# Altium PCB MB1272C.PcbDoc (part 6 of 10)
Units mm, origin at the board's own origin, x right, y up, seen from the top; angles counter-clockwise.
Board outline 101 x 71 mm, 6 copper layers (Top Layer, Signal Layer 1, Signal Layer 2, Signal Layer 3, Signal Layer 4, Bottom Layer), stack 1.552 mm thick; 520 components, 478 nets, 2156 pads, 1894 vias.
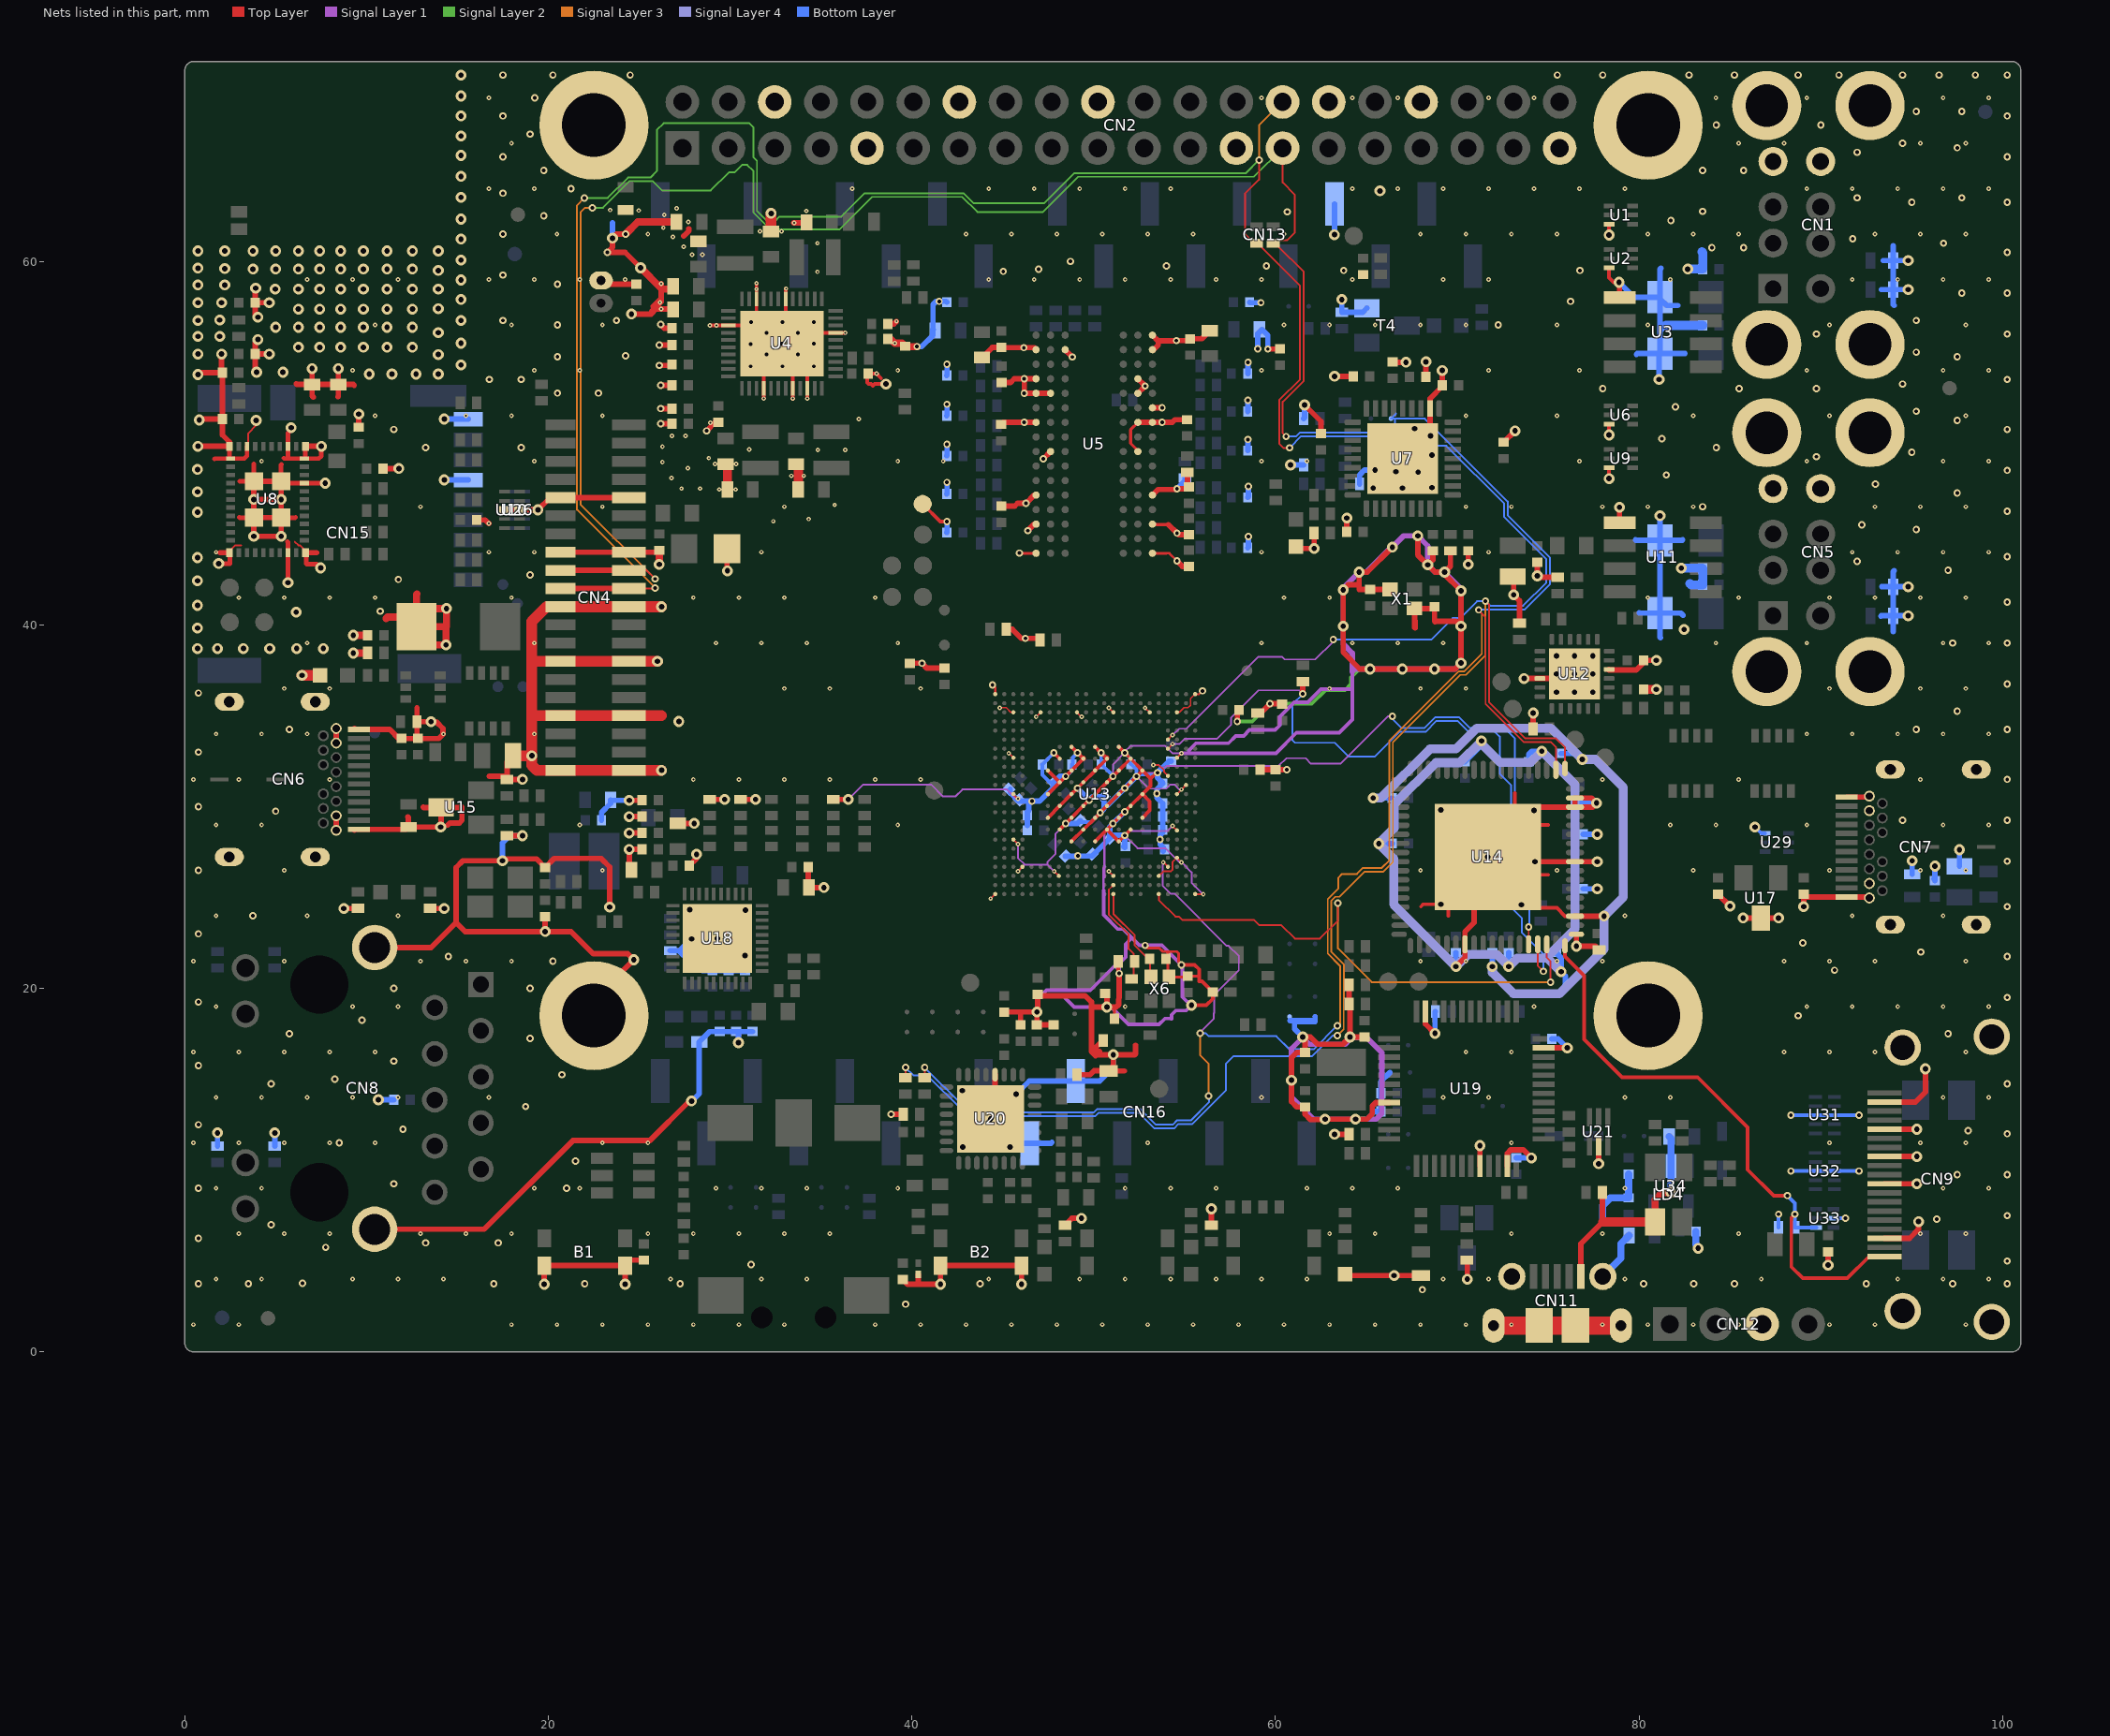
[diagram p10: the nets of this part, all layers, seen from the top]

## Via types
v1: diameter 0.4, hole 0.2, Top Layer to Bottom Layer, tented both sides, 912 vias
v2: diameter 0.25, hole 0.1, Top Layer to Signal Layer 1, tented top, 493 vias
v3: diameter 0.6, hole 0.3, Top Layer to Bottom Layer, tented both sides, 452 vias
v4: diameter 0.25, hole 0.1, Top Layer to Signal Layer 1, tented both sides, 37 vias

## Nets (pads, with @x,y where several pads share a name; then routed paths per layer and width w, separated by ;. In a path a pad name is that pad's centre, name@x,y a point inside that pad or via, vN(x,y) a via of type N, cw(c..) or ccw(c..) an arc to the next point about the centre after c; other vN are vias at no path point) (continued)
GND: B1.1 B1.2 B2.3 B2.4 C1.1 C2.1 C3.1 C4.1 C5.1 C6.1 C7.1 C8.1 C9.1 C10.2 C11.1 C12.1 C13.1 C14.2 C15.1 C16.1 C17.2 C18.1 C19.1 C20.1 C21.1 C22.2 C23.1 C24.1 C25.1 C26.1 C27.1 C28.1 C29.1 C30.1 C31.1 C32.1 C33.1 C34.1 C35.2 C36.2 C37.1 C38.1 C39.1 C40.1 C41.1 C42.1 C43.1 C44.1 C45.1 C46.2 C47.2 C48.2 C49.1 C50.1 C51.1 C52.2 C53.1 C54.1 C55.1 C56.1 C57.2 C58.1 C59.1 C60.2 C61.2 C62.1 C63.1 C64.1 C65.1 C67.1 C68.1 C69.1 C70.2 C71.1 C72.1 C73.1 C74.1 C75.1 C76.2 C77.1 C78.1 C79.1 C80.1 C81.1 C82.1 C83.1 C84.1 C85.1 C86.1 C87.2 C88.1 C89.1 C90.2 C91.2 C92.1 C93.1 C94.1 C95.1 C96.2 C98.2 C99.2 C112.1 C114.1 C115.1 C117.1 C118.1 C119.2 C120.2 C121.1 C122.1 C123.1 C124.1 C125.2 C126.2 C127.2 C128.2 C129.2 C130.2 C131.2 C132.2 C133.1 C134.2 C135.2 C136.1 C137.1 C138.1 C139.1 C140.1 C141.1 C142.1 C143.1 C144.1 C145.1 C146.1 C147.1 C148.1 C149.1 C150.1 C151.1 C152.1 C153.1 C154.1 C155.1 C156.1 C157.1 C158.1 C159.1 C160.1 C161.1 C162.1 C163.1 C164.1 C165.1 C166.1 C167.1 C168.1 C169.1 C170.1 C171.1 C172.1 C173.1 C174.1 C175.1 C176.1 C177.1 C178.1 C179.1 C180.1 C181.1 C182.1 C183.1 C184.1 C185.2 C186.1 C187.1 C188.1 C189.1 C190.1 C191.1 C192.1 C300.1 CN1.B4 CN1.CH1 CN1.CH2 CN1.CH3 CN1.CH4 CN1.T4 CN2.6 CN2.9 CN2.14 CN2.20 CN2.25 CN2.30 CN2.34 CN2.39 CN3.2 CN4.1 CN4.4 CN4.7 CN4.10 CN4.13 CN4.16 CN5.B4 CN5.CH1 CN5.CH2 CN5.CH3 CN5.CH4 CN5.T4 CN6.A1 CN6.A12 CN6.B1 CN6.B12 CN6.SH1 CN6.SH2 CN6.SH3 CN6.SH4 CN7.A1 CN7.A12 CN7.B1 CN7.B12 CN7.SH1 CN7.SH2 CN7.SH3 CN7.SH4 CN8.15 CN8.16 CN9.2 CN9.5 CN9.8 CN9.11 CN9.17 CN9.20 CN9.21 CN9.22 CN9.23 CN11.5 CN11.6 CN11.7 CN11.8 CN11.9 CN11.10 CN11.11 CN12.3 CN13.7 CN15.6 CN15.9 CN16.6 CN16.7 H1.1 H2.1 H3.1 H4.1 LD1.2 LD2.2 LD4.1 LD7.2 LD8.2 R15.1 R23.1 R24.1 R31.1 R36.1 R37.1 R38.2 R39.1 R44.1 R45.1 R46.1 R48.1 R50.1 R51.1 R54.1 R57.1 R66.1 R67.1 R70.2 R80.1 R81.2 R82.1 R83.2 R84.1 R87.2 R91.1 R100.1 R110.2 R111.2 R112.1 R119.1 R129.1 R136.1 R137.1 R139.1 R149.1 R155.2 R159.1 R162.1 R163.1 R164.1 R303.2 SB11.1 SB12.1 SB18.1 T4.2 TP2.1 U1.3 U2.3 U3.1 U4.6 U4.10 U4.15 U4.26 U4.30 U4.32 U4.41 U4.ep U5.A9 U5.B1 U5.B3 U5.B9 U5.D1 U5.D8 U5.E1 U5.E2 U5.E8 U5.F9 U5.G1 U5.G8 U5.G9 U5.J2 U5.J8 U5.M1 U5.M9 U5.P1 U5.P9 U5.T1 U5.T9 U6.3 U7.11 U7.37 U8.1 U8.12 U8.19 U8.21 U8.29 U8.32 U8.33 U8.35 U8.40 U8.42 U8.43 U8.44 U8.45 U8.46 U9.3 U10.3 U10.8 U11.1 U12.10 U12.22 U12.ep U13.1A3 U13.1A5 U13.1A7 U13.1B2 U13.1B4 U13.1B6 U13.1B8 U13.1C1 U13.1C3 U13.1C5 U13.1C7 U13.1C9 U13.1D2 U13.1D4 U13.1D6 U13.1D8 U13.1E1 U13.1E3 U13.1E5 U13.1E7 U13.1E9 U13.1F2 U13.1F4 U13.1F6 U13.1F8 U13.1G1 U13.1G3 U13.1G5 U13.1G7 U13.1G9 U13.1H2 U13.1H4 U13.1H6 U13.1H8 U13.1J3 U13.1J5 U13.1J7 U13.A1 U13.A23 U13.AA5 U13.AA8 U13.AA12 U13.AA16 U13.AA21 U13.AB13 U13.AC1 U13.AC23 U13.C7 U13.C12 U13.C16 U13.C21 U13.D4 U13.F21 U13.H3 U13.K21 U13.P3 U13.P21 U13.V21 U13.W3 U14.43 U14.55 U14.57 U14.63 U14.69 U14.70 U14.e-Pad U15.3 U16.2 U17.3 U18.41 U19.8 U19.20 U19.23 U19.35 U19.47 U20.28 U20.33 U21.2 U23.2 U24.2 U25.2 U26.3 U26.8 U27.2 U28.2 U29.3 U30.2 U31.3 U31.8 U32.3 U32.8 U33.2 U34.2 U35.2 X1.2 X1.4 X6.2 | length 990.5
  Top Layer w0.09: v4(44.83,35.44) 45.191,35.44 45.441,35.19 U13.C21@45.58,35.19 ; U13.W3@53.58,26.19 53.83,26.44 54.178,26.44 ; 54.184,26.44 54.245,26.44 54.33,26.525 54.33,26.955 54.565,27.19 U13.AA5@54.58,27.19 ; U13.AA21@54.59,35.186 54.708,35.186 54.962,35.44 55.185,35.44 55.325,35.575 ; 55.33,35.575 55.33,35.949 55.571,36.19 U13.AC23@55.58,36.19
  Top Layer w0.1: U8.12@2.463,43.975 2.463,44.063 2.775,44.375 3.1,44.375 ; U8.40@3.425,49.825 3.425,50 3.49,50.065 3.49,50.535 3.925,50.97 v3(3.925,51.25) ; 6.05,44.575 6.25,44.375 6.325,44.375 6.638,44.063 U8.21@6.638,43.975 ; v2(44.33,24.94) U13.A1@44.58,25.19 ; v2(45.33,32.94) U13.C16@45.58,32.69 ; U13.C7@45.58,28.19 v2(45.83,27.94) ; U13.C12@45.58,30.69 v2(45.83,30.44) ; v2(45.83,26.44) U13.D4@46.08,26.69 ; v2(46.83,34.94) U13.F21@47.08,35.19 ; v2(47.83,26.44) U13.H3@48.08,26.19 ; U13.K21@49.08,35.19 v4(49.33,34.94) ; v2(50.83,26.44) U13.P3@51.08,26.19 ; v4(50.83,35.44) U13.P21@51.08,35.19 ; v4@52.84,35.43 U13.V21@53.08,35.19 ; v2(54.33,28.94) U13.AA8@54.58,28.69 ; U13.AA5@54.58,27.19 v2(54.83,26.94) ; U13.AA12@54.58,30.69 v2(54.83,30.94) U13.AB13@55.08,31.19 ; U13.AA16@54.58,32.69 v2(54.83,32.94) ; U13.AC1@55.58,25.19 55.595,25.175 v4(56.025,25.175) ; U13.AC23@55.58,36.19 55.8,36.19 v1(55.98,36.37)
  Top Layer w0.12: v1(44.43,36.7) 44.58,36.55 U13.A23@44.58,36.19 ; v1@48.772,54.74 v1@48.772,54.798 ; U5.J8@52.43,49.54 U5.J8@52.43,49.59 ; 54.01,43.94 54.16,43.94 v1(54.58,43.52)
  Top Layer w0.15: v1@45.91,43.94 U5.T1@46.83,43.94 ; C300.1@51.15,18.325 51.15,18.9 51.225,18.975 ; v1@52.83,22.34 52.945,22.225 53.605,22.225 53.805,22.025 54.572,22.025 54.68,21.917 54.68,21.44 v1(54.83,21.29) ; U5.T9@53.18,43.94 U5.T9@53.23,43.94 54.01,43.94 ; 54.075,21.98 54.075,20.7 X6.2@54.15,20.625 54.925,20.625 54.975,20.675 C87.2@55.175,20.675 55.75,20.675 55.8,20.625
  Top Layer w0.16: U5.J8@52.43,49.59 52.03,49.99 52.03,50.74 U5.G8@52.43,51.14
  Top Layer w0.2: v4(28.882,56.482) 29.243,56.482 v4(29.25,56.475) U4.15@29.9,56.475 30.875,56.475 U4.ep@30.9,56.45 ; v2(31.45,58.8) v2(31.45,58.475) U4.10@31.45,57.925 31.45,56.875 v1(32.85,55.475) ; v2(31.85,52.45) U4.26@31.85,53.025 31.85,54.475 v1(32.85,55.475) ; v3(32.255,62.64) v3@32.381,62.514 ; v2@33.05,58.5 U4.6@33.05,57.925 U4.ep@33.05,55.675 ; v2@33.45,52.425 v2(33.45,52.45) U4.30@33.45,53.025 U4.ep@33.45,54.875 ; v2(34.25,52.45) U4.32@34.25,53.025 34.25,54.075 U4.ep@33.45,54.875 ; v2(36.325,56.075) U4.41@35.8,56.075 33.45,56.075 U4.ep@33.05,55.675 ; C26.1@37.537,53.762 37.537,53.338 37.625,53.25 37.757,53.25 37.857,53.15 37.957,53.25 v3(38.575,53.25) ; C26.1@37.6,53.825 v2(38.05,53.825) 38.3,53.575 ; C63.1@39.85,37.91 C63.1@39.87,37.89 ; TP2.1@40.592,46.652 41.554,45.69 v1(41.93,45.69) ; U13.1A5@47.475,30.675 47.475,30.685 U13.1B6@48.12,31.33 ; U13.1A7@47.48,31.99 U13.1B6@48.13,31.34 ; U13.1A3@47.5,29.41 U13.1B4@48.13,30.04 ; v1@47.8,32.95 47.82,32.95 U13.1B8@48.13,32.64 ; U13.1B4@48.12,30.05 48.14,30.05 U13.1C5@48.78,30.69 v1(49.105,31.015) U13.1D6@49.43,31.34 50.05,31.96 U13.1E7@50.05,32.01 ; U13.1B6@48.12,31.35 U13.1B6@48.12,31.33 ; U13.1B2@48.13,28.74 U13.1C3@48.78,29.39 U13.1D4@49.43,30.04 U13.1E5@50.08,30.69 U13.1F6@50.73,31.34 v1(51.055,31.665) U13.1G7@51.38,31.99 U13.1H8@52.03,32.64 ; U13.1C1@48.78,28.09 U13.1D2@49.43,28.74 U13.1E3@50.08,29.39 U13.1F4@50.73,30.04 U13.1G5@51.38,30.69 v1(51.705,31.015) U13.1H6@52.03,31.34 U13.1J7@52.68,31.99 ; U13.1C7@48.78,32 U13.1C7@48.78,31.99 ; U13.1C9@48.78,33.29 v1@49.11,32.96 ; v1@49.1,32.98 U13.1D8@49.42,32.66 ; U13.1D8@49.43,32.65 U13.1D8@49.42,32.66 ; U13.1E9@50.07,33.29 v1@50.395,32.965 ; U13.1E1@50.08,28.09 U13.1F2@50.73,28.74 ; U13.1E7@50.08,32 50.09,32 U13.1F8@50.73,32.64 ; v1(50.405,32.965) U13.1F8@50.7,32.67 ; R303.2@51.35,21.35 51.35,20.55 51.4,20.5 ; U13.1G9@51.38,33.29 v1(51.705,32.965) U13.1H8@52.03,32.64 ; U13.1H2@52.03,28.74 v1(51.705,28.415) U13.1G1@51.38,28.09 U13.1F2@50.73,28.74 ; U13.1J3@52.68,29.39 53.075,29.785 53.075,30.295 U13.1J5@52.68,30.69 ; U5.P9@53.23,45.54 53.25,45.52 54.11,45.52 ; v1(53.505,31.865) 53.445,31.865 53.125,31.545 ; 54.075,21.98 54.095,22 ; v1(54.83,21.29) 55.555,21.29 55.8,21.045 55.8,20.625 55.8,20.4 55.95,20.4 C89.1@56.55,19.8 56.55,19.425 56.2,19.075 v3(55.375,19.075) ; v1(59.7,35.66) 59.73,35.63 C67.1@60.33,35.63 ; C67.1@60.3,35.66 C67.1@60.33,35.63 ; C67.1@60.34,35.62 C67.1@60.33,35.63 ; C67.1@60.36,35.63 C67.1@60.33,35.63 ; 68,24.5 68.125,24.625 v3(69.1,24.625) ; 69.5,24 69.5,25.05 70.925,26.475 v3(71.675,27.225) ; 73.156,30.75 U14.e-Pad@73.156,28.706 ; 75,26.25 U14.e-Pad@72.65,26.25 ; 75,29 73.45,29 U14.e-Pad@73.156,28.706 ; U14.57@76.475,23.975 75.925,23.975 75.475,24.425 74.475,24.425 U14.e-Pad@72.65,26.25 ; v3(78.35,48.05) U9.3@78.35,48.65 ; v3(78.35,50.45) U6.3@78.35,51.05 ; U2.3@78.35,59.65 78.35,59.1 78.6,58.85 v3(78.9,58.85) ; v3(78.35,61.45) U1.3@78.35,62.05 ; v1(32.85,55.475) U4.ep@33.05,55.675 ; v1(32.85,55.475) U4.ep@33.45,54.875 ; U13.1B6@48.12,31.33 U13.1B6@48.13,31.34 ; U13.1B6@48.13,31.34 U13.1C7@48.78,31.99 ; U13.1C7@48.78,31.99 49.42,32.63 U13.1D8@49.42,32.66 ; U13.1F2@50.73,28.74 v1(51.055,29.065) U13.1G3@51.38,29.39 v1(51.705,29.715) U13.1H4@52.03,30.04 U13.1J5@52.68,30.69 ; U13.1H8@52.03,32.64 U13.1J7@52.68,31.99 ; U13.1J5@52.68,30.69 53.125,31.135 53.125,31.545 ; U13.1J7@52.68,31.99 53.125,31.545 ; v3(71.675,27.225) U14.e-Pad@73.156,28.706 ; v3(71.675,27.225) U14.e-Pad@72.65,26.25
  Top Layer w0.25: 1.625,49.125 1.65,49.15 U8.1@2.525,49.15 ; v3(1.863,43.375) 2.475,43.375 2.475,43.963 U8.12@2.463,43.975 ; U8.42@2.463,49.825 2.463,49.212 U8.1@2.525,49.15 ; 3,45.925 3.025,45.9 3.775,45.9 U8.44@3.8,45.9 ; 3.025,47.9 U8.43@3.8,47.9 3.8,48.85 ; U8.40@3.425,49.825 3.425,49.3 3.275,49.15 U8.1@2.525,49.15 ; U8.46@5.3,45.9 6.075,45.9 6.1,45.925 ; 5.325,48.825 5.3,48.8 U8.45@5.3,47.9 5.4,47.8 U8.29@6.575,47.8 v3(7.725,47.8) ; 5.45,49.175 5.475,49.15 U8.32@6.575,49.15 ; 5.65,44.575 5.675,44.55 U8.19@5.675,43.975 v3(5.675,42.325) ; 5.675,49.25 U8.35@5.675,49.825 5.675,50.55 5.85,50.725 v3(5.85,50.85) ; U8.21@6.638,43.975 6.675,43.937 6.675,43.375 6.703,43.347 7.266,43.347 v3(7.475,43.137) ; U8.33@6.638,49.825 6.638,49.212 U8.32@6.575,49.15 ; v3(7.512,49.825) 7.512,49.287 7.375,49.15 U8.32@6.575,49.15
  Top Layer w0.3: v3(0.725,49.825) U8.42@2.463,49.825 2.463,50.062 2.075,50.45 C34.1@2.075,51.325 ; v3(0.725,53.775) 0.825,53.875 C24.1@2.075,53.875 ; v3(0.8,51.275) 0.875,51.275 0.925,51.325 C34.1@2.075,51.325 ; 1.95,43.975 U8.12@2.463,43.975 ; v3(2.025,54.9) 2.025,53.925 C24.1@2.075,53.875 ; v3@3.875,55.55 C19.1@3.875,54.9 ; v3@3.875,57.075 C8.1@3.875,57.725 ; v3@3.875,58.375 C8.1@3.875,57.725 ; v3(3.95,53.9) 3.875,53.975 C19.1@3.875,54.9 ; v3(4.65,54.9) C19.1@3.875,54.9 ; v3(4.65,57.725) C8.1@3.875,57.725 ; v3(5.3,46.9) U8.45@5.3,47.9 U8.43@3.8,47.9 v3(3.8,46.9) ; 6.125,53.275 6.175,53.225 C28.1@7,53.225 ; U8.21@6.638,43.975 7.25,43.975 ; U8.33@6.638,49.825 v3(7.512,49.825) ; v3(7,54.1) C28.1@7,53.225 ; 7.075,52.525 7,52.6 C28.1@7,53.225 ; CN6.B1@8.33,28.7 CN6.B1@8.33,29.5 ; CN6.B12@8.33,33.5 CN6.B12@8.33,34.3 ; 8.425,52.55 8.45,52.575 C29.1@8.45,53.225 ; v3(8.45,54.1) C29.1@8.45,53.225 ; v3(8.75,24.4) R66.1@9.525,24.4 ; 9.325,53.175 9.275,53.225 C29.1@8.45,53.225 ; CN6.A12@9.33,28.7 9.38,28.75 CN6.A12@9.58,28.75 12.175,28.75 U16.2@12.3,28.875 ; CN6.A1@9.33,34.3 9.38,34.25 CN6.A1@9.58,34.25 11.275,34.25 11.775,33.75 C69.1@11.925,33.75 C70.2@12.825,33.75 ; C37.1@9.575,50.875 v3(9.575,51.6) ; CN8.15@10.45,6.75 16.475,6.75 21.35,11.625 25.576,11.625 27.751,13.8 v3(27.875,13.8) ; CN8.16@10.45,22.25 13.55,22.25 14.925,23.625 ; C45.1@10.9,48.6 v3(11.775,48.6) ; 12.275,29.425 12.3,29.4 U16.2@12.3,28.875 ; 12.775,35.425 R45.1@12.775,34.675 ; 13.125,29.975 13.15,29.95 U15.3@14.1,29.95 ; R67.1@13.5,24.4 v3(14.275,24.4) ; 14.467,28.983 14.584,29.1 15.1,29.1 15.25,29.25 15.25,29.975 15.225,29.95 U15.3@14.1,29.95 ; C49.1@16.05,45.775 16.525,45.775 v4(16.725,45.575) ; 16.75,31.675 17.55,31.675 R48.1@17.725,31.5 ; U10.8@17.59,46.325 U10.3@18.41,46.325 19.424,46.325 v3(19.426,46.327) ; R57.1@17.725,28.4 v3(18.575,28.4) ; C71.1@18.05,32.8 17.725,32.475 R48.1@17.725,31.5 ; v3(18.575,31.5) R48.1@17.725,31.5 ; v3@19.577,46.327 v3(19.426,46.327) ; v3(19.775,3.725) B1.2@19.775,4.75 B1.1@24.225,4.75 ; C86.1@19.825,23.95 v3(19.825,23.125) ; CN4.13@20.675,44 CN4.13@24.425,44 26,44 C51.1@26.1,44.1 ; H3.1@22.5,18.5 22.5,19.375 v3(24.7,21.575) 24.365,21.91 22.465,21.91 21.25,23.125 v3(19.825,23.125) ; CN3.2@22.9,58.95 23.1,58.75 C7.1@24.85,58.75 ; v3(23.375,24.475) 23.375,26.675 22.9,27.15 20.325,27.15 C82.1@19.825,26.65 19.35,27.125 17.575,27.125 v3(17.475,27.025) 15.3,27.025 14.925,26.65 14.925,23.625 ; v3(24.225,3.725) B1.1@24.225,4.75 ; v1(24.25,61.5) 23.75,61.5 v3(23.525,61.275) 23.525,60.775 v1(23.25,60.5) 24.225,60.5 v3(25.075,59.65) ; CN4.16@24.425,47 CN4.16@20.675,47 20.099,47 v3(19.426,46.327) ; v3(24.45,28.55) C77.1@25.15,28.55 ; v3(24.45,29.45) C75.1@25.15,29.45 ; v3(24.45,30.35) C74.1@25.15,30.35 ; C80.1@24.575,26.525 24.45,26.65 v3(24.45,27.65) C78.1@25.15,27.65 ; v3(24.575,57.1) 25.65,57.1 25.675,57.125 ; C114.1@25.25,5.05 24.525,5.05 B1.1@24.225,4.75 ; v1(26.1,54.275) 26.75,54.275 C27.1@26.8,54.325 C27.1@26.775,54.35 ; v1(26.1,55.4) C20.1@26.8,55.4 ; v2(26.144,57.744) 25.925,57.525 25.925,57.5 ; v1(26.175,51.075) C39.1@26.8,51.075 ; v1(26.175,51.9) C31.1@26.8,51.9 ; v1(26.175,53.175) C32.1@26.8,53.175 ; v1(26.175,56.525) 26.375,56.325 C15.1@26.8,56.325 ; v2(26.2,58.775) 26.2,58.525 26.2,57.95 ; C9.1@26.85,57.375 v2(26.214,57.375) 25.925,57.375 ; C76.2@27.125,29.075 v3(28.025,29.075) ; 27.45,61.4 27.725,61.675 27.725,61.8 ; C79.1@27.75,26.75 28.15,27.15 v3(28.15,27.375) ; v1(28.7,50.675) 29.175,51.15 C33.1@29.35,51.15 ; R50.1@28.875,30.4 v3(29.7,30.4) ; C52.2@29.825,44.2 29.825,42.95 v3(29.85,42.975) ; R51.1@30.575,30.4 v3(31.4,30.4) ; C5.1@32.255,61.701 32.25,61.696 32.227,61.673 C5.1@32.25,61.65 C5.1@32.4,61.5 ; v2@33.5,62.125 v2(33.525,62.125) 33.95,62.125 C3.1@34.2,61.875 ; C81.1@34.3,26.675 34.3,25.575 C85.1@34.325,25.55 v3(35.155,25.55) ; R54.1@35.675,30.4 v3(36.5,30.4) ; C10.2@38.6,56.575 C10.2@38.65,56.525 ; C10.2@38.684,56.562 39.012,56.562 v2(39.15,56.7) ; v1(38.85,13.075) R87.2@39.525,13.075 ; C115.1@39.5,3.975 39.75,3.725 40.35,3.725 ; C12.1@39.62,55.33 40.19,55.33 v1@40.2,55.32 ; C63.1@39.87,37.89 v1(40.55,37.89) 40.825,37.615 C64.1@41.79,37.615 ; U35.2@40.35,4.263 40.35,3.725 ; C13.1@43.88,54.72 44.42,55.26 C14.2@44.92,55.26 44.96,55.26 44.97,55.25 v1(46.16,55.25) 46.72,55.25 U5.B1@46.83,55.14 ; U20.28@44.575,15.25 44.575,13.075 v3(44.325,12.825) 44.425,12.825 45.75,14.15 v3(45.725,14.175) ; C36.2@44.91,51.03 45.02,51.14 v1(46.18,51.14) U5.G1@46.83,51.14 ; C47.2@44.92,46.53 44.93,46.54 45.66,46.54 45.81,46.69 v1(46.28,46.69) 46.73,47.14 U5.M1@46.83,47.14 ; C22.2@44.94,53.34 45.43,53.34 45.63,53.54 v1(46.18,53.54) ; C92.1@45.075,18.7 45.975,18.7 ; R37.1@45.19,39.76 45.52,39.76 46.02,39.26 v1(46.24,39.26) 46.96,39.26 R38.2@47.05,39.17 ; C94.1@45.975,18 45.975,18.7 ; v3(46.025,3.725) B2.4@46.025,4.75 B2.3@41.575,4.75 v3(41.575,3.725) 40.35,3.725 ; v1(46.37,45.18) 46.73,45.54 U5.P1@46.83,45.54 ; U5.D1@46.83,53.54 v1(46.18,53.54) ; v1(47.23,49.14) U5.J2@47.63,49.54 ; U5.E2@47.63,52.74 U5.E1@46.83,52.74 v1(46.18,52.74) v1(46.18,53.54) ; C96.2@47.8,18 C95.1@46.875,18 v3(46.875,18.7) ; R110.2@48.425,6.975 48.8,7.35 v3(49.325,7.35) ; U5.B3@48.43,55.14 v1@48.772,54.798 ; R84.1@49.075,15.25 49.8,15.25 50.025,15.475 R83.2@50.8,15.475 ; U13.1D8@49.43,32.64 U13.1D8@49.43,32.65 ; 50.32,16.52 49.875,16.52 ; v1@50.395,32.965 v1(50.405,32.965) ; R82.1@50.53,17.175 49.875,16.52 ; U13.1F8@50.7,32.67 U13.1F8@50.71,32.67 ; C91.2@50.725,19.675 v3(50.725,18.975) ; R83.2@50.825,15.45 R83.2@50.8,15.475 ; R83.2@51.1,15.461 51.686,15.461 ; v1(51.4,20.82) 51.4,20.5 51.4,19.775 51.375,19.1 51.225,18.975 v3(50.725,18.975) ; 52.3,16.875 52.3,16.4 52.25,16.35 v3(51.075,16.35) ; U5.G8@52.43,51.14 U5.G9@53.23,51.14 v1(53.76,51.14) 54.32,51.14 54.47,51.29 C35.2@55.14,51.29 ; U5.E8@52.43,52.74 v1(52.83,53.14) U5.D8@52.43,53.54 ; U5.M9@53.23,47.14 53.54,47.45 54.54,47.45 v1(54.58,47.49) 55.12,47.49 55.12,47.6 55.155,47.635 R15.1@55.155,48.39 ; U5.F9@53.23,51.94 v1(53.76,51.94) ; U5.B9@53.23,55.14 53.29,55.14 53.55,55.4 53.55,55.62 ; U5.A9@53.23,55.94 53.55,55.62 ; 54.11,45.52 v1(54.58,45.05) 54.67,44.96 C48.2@55.23,44.96 ; v1(54.58,43.52) 54.88,43.22 C57.2@55.23,43.22 ; C11.1@56.39,56.18 55.95,55.74 C17.2@55.3,55.74 55.2,55.64 v1(54.55,55.64) 54.53,55.62 53.55,55.62 ; R111.2@56.475,6.975 v3(56.475,7.875) ; v1(57.9,34.69) 57.9,35.22 C68.1@58,35.32 ; R44.1@59.025,35.15 59.19,35.15 v1(59.7,35.66) C67.1@60.3,35.66 ; C72.1@59.155,32.04 C73.1@60.005,32.04 60.018,32.027 v1(60.618,32.027) ; v1(59.58,55.18) 60.18,55.18 C18.1@60.2,55.16 ; LD1.2@61.125,44.3 61.225,44.2 v3(62.125,44.2) R23.1@62.125,45.05 ; v3(61.6,52.1) 62.5,51.2 C38.1@62.5,50.525 ; v3(63.25,11.975) R91.1@64.05,11.975 ; v3(63.25,53.675) C23.1@64.025,53.675 ; LD7.2@63.825,4.275 63.9,4.2 v3(66.525,4.2) LD8.2@68,4.2 ; C50.1@63.925,45.125 v3(63.925,45.875) ; R80.1@64.05,20.2 R81.2@64.05,19.15 64.1,19.1 v3(64.1,17.325) ; C93.1@64.9,17.325 v3(64.1,17.325) ; U19.8@66.25,13.725 65.525,13.725 65.325,13.525 65.325,13.1 65.025,12.8 v3(64.4,12.8) v3(62.725,12.8) 62.75,12.775 61.925,12.775 61.625,13.075 C99.2@61.625,13.475 61.175,13.475 60.875,13.775 v3(60.875,14.95) 60.875,16.175 61.175,16.475 C98.2@61.625,16.475 61.625,17.325 61.925,17.325 62.325,16.925 63.7,16.925 v3(64.1,17.325) ; X1.2@66.3,41.95 C58.1@65.2,41.95 64.6,41.95 64.6,42.2 ; v3(66.425,44.275) 65.05,42.9 v3(64.6,42.9) 64.6,42.2 ; C21.1@66.45,54.475 66.475,54.45 v3(67.175,54.45) ; U7.37@67,49.15 68.5,50.65 U7.11@68.5,51.9 68.5,52.45 69.175,53.125 C30.1@69.175,53.175 v3(69.175,54) ; 67.675,40.225 67.675,39.825 67.65,39.85 X1.4@67.65,40.9 68.65,40.9 C59.1@68.75,41 68.75,40.2 ; v3(67.825,44.9) 67.825,43.85 v3(68.375,43.3) ; U19.47@68.25,18.725 68.25,18.05 v3(68.775,17.525) ; C25.1@68.275,53.65 v3(68.275,54.475) ; C53.1@68.65,44.075 68.65,43.575 v3(68.375,43.3) ; 68.775,40.175 68.75,40.2 ; v3@69.238,42.837 v3(70.2,41.875) v3(70.2,39.925) ; R24.1@69.625,44.075 69.625,43.225 v3(69.3,42.9) 68.775,42.9 v3(68.375,43.3) ; v3(69.925,21.2) 70.425,21.7 U14.43@70.425,22.425 70.425,23.125 70.925,23.625 U14.e-Pad@70.925,26.475 ; R112.1@70.525,5.05 70.55,5.025 v3(70.55,4) ; v3(70.6,43.325) C54.1@70.6,44.075 ; U19.20@71.25,10.225 v3(71.25,11.35) ; C40.1@72.55,50.05 v3(73.175,50.675) ; U19.23@72.75,10.225 72.75,10.925 72.95,11.125 73.625,11.125 v3(74.075,10.675) ; C55.1@73.05,42.65 73.1,42.6 v3(73.1,41.65) 73.425,41.325 R36.1@73.425,40.1 ; U14.e-Pad@73.45,29 74.425,29.975 U14.69@76.475,29.975 ; v3(73.675,37.05) U12.10@74.55,37.05 75.2,37.05 v3(75.45,37.3) ; R46.1@74.175,34.275 v3(74.175,35.15) ; v3(74.275,26.975) U14.63@76.475,26.975 v3(77.7,26.975) ; C56.1@74.4,43.45 v3(74.4,42.7) 74.475,42.625 R31.1@75.525,42.625 ; U19.35@74.75,16.725 v3(76.05,16.725) ; U14.57@76.475,23.975 v3(78.075,23.975) v3@78.05,24 ; U14.55@76.55,22.975 v3(76.55,22.325) 77.6,22.325 R70.2@77.8,22.125 ; CN11.5@76.8,4.15 76.8,5.95 78,7.15 77.975,7.175 R100.1@77.975,8.775 ; v3(77.775,10.35) U21.2@77.775,11.295 ; U12.22@78.35,37.55 78.35,37.52 79.845,37.52 80.25,37.925 C62.1@80.25,38.05 v3(80.95,38.05) ; v3(78.9,58.85) 78.925,58.825 U3.1@78.925,58.005 ; U11.1@78.925,45.63 v3(78.925,46.475) ; C83.1@84.35,25.175 v3(85,24.525) ; v3(85.725,23.875) U17.3@86.7,23.875 v3(87.675,23.875) ; v3(89.05,24.5) C84.1@89.05,25.175 89.2,25.025 CN7.A1@91.42,25.025 92.62,25.025 CN7.B12@92.67,24.975 ; v3(90.4,4.775) C112.1@90.4,5.5 ; CN7.A12@91.42,30.525 92.62,30.525 CN7.B1@92.67,30.575 ; CN9.17@93.5,6.25 94.875,6.25 95.375,6.75 v3(95.375,7.171) ; CN9.11@93.5,9.25 v3(95.275,9.25) ; CN9.8@93.5,10.75 v3(95.275,10.75) ; CN9.5@93.5,12.25 v3(95.275,12.25) ; CN9.2@93.5,13.75 95.2,13.75 95.75,14.3 v3(95.75,15.575) ; C34.1@2.075,51.325 C24.1@2.075,53.875 ; U8.44@3.8,45.9 v3(3.8,46.9) ; U8.44@3.8,45.9 3.775,45.9 3.8,45.875 v3(3.8,44.875) v3(5.3,44.875) U8.46@5.3,45.9 ; U8.44@3.8,45.9 U8.46@5.3,45.9 ; v3(3.8,46.9) v3(5.3,46.9) U8.46@5.3,45.9 ; C28.1@7,53.225 C29.1@8.45,53.225 ; U16.2@12.3,28.875 v3(14.075,28.875) 14.1,28.9 U15.3@14.1,29.95 ; R45.1@12.775,34.675 12.775,33.8 C70.2@12.825,33.75 ; R45.1@12.775,34.675 v3(13.55,34.675) 13.825,34.675 14.2,34.3 14.2,33.975 13.975,33.75 C70.2@12.825,33.75 ; 14.925,23.625 15.425,23.125 v3(19.825,23.125) ; 25.675,57.125 25.675,57.25 25.863,57.438 ; 25.675,57.125 25.925,57.375 ; 25.863,57.438 25.925,57.5 ; 25.863,57.438 25.925,57.375 ; 25.863,57.438 25.775,57.525 26.2,57.95 ; 25.925,57.375 25.925,57.5 ; 25.925,57.5 26.2,57.775 26.2,57.95 ; 45.975,18.7 v3(46.875,18.7) ; v3(46.875,18.7) 46.925,18.75 C90.2@46.925,19.675 47,19.6 49.525,19.6 49.875,19.25 49.875,19 ; 49.875,16.52 49.875,19 ; 49.875,16.52 50.095,16.3 50.145,16.35 v3(51.075,16.35) ; 49.875,19 49.9,18.975 v3(50.725,18.975) ; R83.2@50.8,15.475 51.075,15.75 v3(51.075,16.35) ; 64.6,42.2 64,42.2 v3(63.725,41.925) 63.725,38.495 64.645,37.575 69.875,37.575 v3(70.2,37.9) v3(70.2,39.925) ; 68.75,40.2 69.925,40.2 v3(70.2,39.925) ; U14.69@76.475,29.975 77.438,29.975 v3(77.662,30.2) 77.387,30.475 U14.70@76.475,30.475 U14.69@76.475,29.975
  Top Layer w0.4: v3(9.275,38.45) R39.1@10.05,38.45 ; v3(9.275,39.425) C61.2@10.05,39.425 ; 11.075,40.35 11.15,40.425 12.225,40.425 C60.2@12.75,39.9 ; C60.2@12.725,38.9 v3(14.375,38.9) ; 12.775,41.7 12.75,41.675 C60.2@12.75,40.9 ; v3@14.4,38.9 v3(14.375,38.9) ; v3(14.4,40.9) 14.4,39.9 ; v3@14.425,40.9 C60.2@12.75,40.9 ; v1(24.25,61.5) 24.925,62.175 C2.1@27.05,62.175 ; v3(25.075,59.65) 26.2,58.525 26.25,58.475 C6.1@26.6,58.475 ; v3(26.1,43.325) C51.1@26.1,44.1 ; C16.1@38.751,55.801 v2(39.053,55.5) 39.45,55.5 C12.1@39.62,55.33 39.64,55.31 v1(40.28,55.31) ; LD4.1@80.875,7.15 80.875,8.375 81.275,8.775 v3(81.75,8.775) ; C60.2@12.75,39.9 14.4,39.9 ; C60.2@12.75,39.9 C60.2@12.75,40.9 ; v3(14.375,38.9) 14.375,39.875 14.4,39.9
  Top Layer w0.5: C4.1@28.125,61.1 C4.1@28.25,61.1 ; C41.1@29.75,48.85 29.85,48.75 C42.1@29.85,47.45 ; C43.1@33.625,48.85 33.625,48.75 33.75,48.625 C44.1@33.75,47.45 ; 78,7.15 LD4.1@80.875,7.15 ; C65.1@80.25,36.45 v3(80.95,36.45)
  Top Layer w0.6: v3(6.45,37.225) LD2.2@7.45,37.225 ; C71.1@18.05,32.8 v3(19.091,32.8) ; v3(26,38) CN4.7@24.425,38 CN4.7@20.675,38 19.138,38 19.091,37.952 ; v3(26.225,32) CN4.1@24.425,32 CN4.1@20.675,32 19.361,32 19.091,32.27 v3(19.091,32.8) ; 26.225,35 CN4.4@24.425,35 CN4.4@20.675,35 19.113,35 19.091,35.022 ; v3(26.225,41) CN4.10@24.425,41 CN4.10@20.675,41 20.557,41 20.554,41.003 19.903,41.003 19.091,40.191 19.091,37.952 ; C5.1@32.25,61.65 32.25,61.696 32.25,62.635 v3(32.255,62.64) ; v3(19.091,32.8) 19.091,35.022 ; 19.091,35.022 19.091,37.952
  Top Layer w1: CN11.9@72,1.45 CN11.10@74.5,1.45 CN11.11@76.5,1.45 CN11.8@79,1.45
  Signal Layer 1 w0.1: v3(36.5,30.4) 37.315,31.215 41.055,31.215 41.705,30.565 42.4,30.565 42.775,30.94 45.219,30.94 45.719,30.44 v2(45.83,30.44) ; v2(45.83,26.44) 46.205,26.815 ; v2(45.83,27.94) 45.83,27.19 46.205,26.815 ; v2(47.83,26.44) 47.455,26.815 ; v1(48.455,29.065) 47.905,28.515 47.905,27.404 47.455,26.954 47.455,26.815 ; v1(51.055,31.665) 51.055,32.315 v1(51.705,32.965) 51.705,33.015 52.03,33.34 53.93,33.34 54.33,32.94 v2(54.83,32.94) ; v1(53.505,31.865) 52.555,31.865 v1(52.355,31.665) 53.03,30.99 53.991,30.99 54.216,31.215 54.444,31.215 54.719,30.94 v2(54.83,30.94) ; v2(54.33,28.94) 54.055,28.665 51.955,28.665 v1(51.705,28.415) 52.405,27.715 53.944,27.715 54.719,26.94 v2(54.83,26.94) 55.388,26.382 55.388,25.807 56.02,25.175 v4(56.025,25.175) ; 46.205,26.815 47.455,26.815
  Signal Layer 1 w0.13: 50.525,25.425 50.525,26.05 ; 50.625,26.695 50.6,26.67 ; v1(51.055,29.065) 50.6,28.61 50.6,26.67 ; 50.525,26.05 50.6,26.125 50.6,26.67 ; 50.525,26.05 50.525,26.595 50.6,26.67
  Signal Layer 1 w0.2: v3(46.875,18.7) 46.875,19.36 47.08,19.565 ; 50.55,25.379 50.55,24.045 51.33,23.265 51.607,23.265 52.143,22.728 ; v1(51.4,20.82) v1@51.4,20.995 ; v2(54.83,32.94) 55.23,32.94 ; 64.23,37.42 64.23,36.465 ; 47.08,19.565 48.33,19.565 48.92,18.975 v3(50.725,18.975) 50.966,18.975 51.916,18.025 53.599,18.025 53.914,18.34 54.245,18.34 54.262,18.323 54.275,18.335 54.275,18.548 54.509,18.782 55.082,18.782 v3(55.375,19.075) 55.335,19.075 54.88,19.53 54.88,21.24 v1(54.83,21.29) 53.755,22.365 v1(52.83,22.365) 52.507,22.365 52.143,22.728 ; 47.08,19.565 47.415,19.9 49.815,19.9 51.155,21.24 v1@51.4,20.995 ; v1@51.4,20.995 51.4,21.36 51.755,21.715 51.755,22.44 52.043,22.728 52.143,22.728 ; 55.23,32.94 60.026,32.94 61.151,34.065 63.505,34.065 64.23,34.79 64.23,36.465 ; 55.23,32.94 55.23,33.091 55.629,33.49 57.414,33.49 57.814,33.89 58.241,33.89 58.566,34.215 59.98,34.215 60.233,34.468 60.233,34.943 61.03,35.74 61.78,35.74 62.505,36.465 64.23,36.465
  Signal Layer 1 w0.3: v3(61.5,17.325) v3@61.5,17.3 ; v3@61.513,17.312 v3@61.5,17.3 ; v3@64.08,17.305 v3@64.1,17.305 ; v3(64.1,17.325) v3@64.1,17.305 ; 64.23,37.42 64.23,37.575 ; v3(66.425,44.275) v3@66.555,44.405 ; v3@61.5,17.3 60.875,16.675 v3(60.875,14.95) 60.875,14.02 62.095,12.8 v3(62.725,12.8) v3(64.4,12.8) 65.54,12.8 65.855,13.115 65.855,16.465 65.015,17.305 v3@64.1,17.305 ; v3@61.5,17.3 61.5,17.275 61.85,16.925 63.825,16.925 64.1,17.2 v3@64.1,17.305 ; 64.23,37.575 v3(65.2,37.575) v3(66.975,37.575) v3(68.75,37.575) 69.875,37.575 v3(70.2,37.9) v3(70.2,39.925) v3(70.2,41.875) 70.2,42 v3(69.3,42.9) 68.775,42.9 v3(68.375,43.3) 68.375,44.35 v3(67.825,44.9) 67.05,44.9 v3@66.555,44.405 ; 64.23,37.575 64.23,38.44 63.725,38.945 v3(63.725,39.925) v3(63.725,41.925) 63.725,42.025 v3(64.6,42.9) 64.99,42.9 66.495,44.405 v3@66.555,44.405
  Signal Layer 2 w0.2: v1(57.9,34.69) 58.73,34.69 v1(59.7,35.66) 62,35.66 62.756,36.416 63.831,36.416 64.155,36.74 64.155,37.115 64.594,37.554 v3@64.922,37.554
  Signal Layer 2 w0.3: v3@0.7,49.8 v3(0.725,49.825) ; v3@0.725,51.35 v3(0.8,51.275) ; CN6.B1@8.33,28.7 CN6.B1@8.33,29.5 ; CN6.B12@8.33,33.5 CN6.B12@8.33,34.3
  Signal Layer 3 w0.3: CN6.B1@8.33,28.7 CN6.B1@8.33,29.5 ; CN6.B12@8.33,33.5 CN6.B12@8.33,34.3
  Signal Layer 4 w0.3: CN6.B1@8.33,28.7 CN6.B1@8.33,29.5 ; CN6.B12@8.33,33.5 CN6.B12@8.33,34.3
  Signal Layer 4 w0.5: v3(65.375,30.475) 65.8,30.475 68.498,33.173 69.928,33.173 71.07,34.315 75.16,34.315 v3(76.875,32.6) 77.595,32.6 79.13,31.065 79.13,25.03 v3(78.075,23.975) 78.075,22.16 75.63,19.715 73.08,19.715 71.925,20.87 v3(71.925,21.2) ; 74.955,21.74 76.48,23.265 76.48,31.22 v3(74.65,33.05) 74.025,32.425 72.367,32.425 71.33,33.462 v3(71.33,33.615) 70.13,32.415 68.83,32.415 66.53,30.115 66.53,28.815 v3(65.68,27.965) 66.505,27.14 66.505,24.62 v3(69.925,21.2) 70.59,21.865 72.179,21.865 72.825,21.219 v3(72.825,21.2) 73.29,21.665 74.96,21.665 v3(75.708,20.917)
  Bottom Layer w0.2: C146.1@47.15,32.325 47.165,32.325 v1(47.805,32.965) ; C146.1@47.17,32.31 47.17,31.755 47.592,31.333 C148.1@47.812,31.333 ; v1(48.455,31.665) 48.49,31.665 48.8,31.975 C145.1@48.8,32.14 ; C145.1@48.78,32.12 C145.1@48.8,32.14 ; C145.1@48.8,32.31 C145.1@48.8,32.14 ; v1(49.105,32.965) 48.85,32.71 48.85,32.19 C145.1@48.8,32.14 ; C155.1@49.261,29.234 49.339,29.156 49.846,29.156 v1(50.355,29.665) ; v1(50.405,32.965) 50.405,32.445 C144.1@50.5,32.35 ; C144.1@50.42,32.33 51.055,31.695 v1(51.055,31.665) ; v1(51.705,32.965) 51.995,32.675 52.005,32.363 C143.1@52.04,32.33 52.075,32.33 52.355,32.05 v1(52.355,31.665) 52.465,31.775 53.415,31.775 v1(53.505,31.865) ; v3(86.375,28.875) 86.725,28.525 U29.3@86.925,28.525 ; R164.1@87.675,6.85 v1(87.675,7.575) ; v1(88.35,9.95) U32.8@89.7,9.95 U32.3@90.75,9.95 v1(92.1,9.95) ; v1(88.35,13.025) U31.8@89.7,13.025 U31.3@90.75,13.025 v1(92.1,13.025) ; U33.2@90.7,7.35 v1(91.35,7.35)
  Bottom Layer w0.3: R163.1@1.8,11.325 v3(1.8,12.05) ; R162.1@4.95,11.325 v3(4.95,12.05) ; CN6.B1@8.33,28.7 CN6.B1@8.33,29.5 ; CN6.B12@8.33,33.5 CN6.B12@8.33,34.3 ; v3(10.65,13.875) C183.1@11.5,13.875 ; v3(14.275,47.975) CN15.6@15.6,47.975 ; v3(14.275,51.325) CN15.9@15.6,51.325 ; v3(17.475,27.025) 17.475,28 17.875,28.4 v3(18.575,28.4) ; U26.3@17.89,46.325 U26.8@18.71,46.325 19.424,46.325 v3(19.426,46.327) ; C157.1@22.925,29.25 22.925,29.675 23.425,30.175 C151.1@23.425,30.375 23.45,30.35 v3(24.45,30.35) ; v3(23.525,61.275) 23.525,62.125 ; R155.2@26.7,22.075 27.225,22.075 ; v3(27.875,13.8) 27.9,13.8 28.3,14.2 C180.1@28.3,17.05 28.875,17.625 C179.1@29.425,17.625 C178.1@30.325,17.625 C178.1@30.38,17.625 ; v3(30.455,17.015) 30.455,17.55 C178.1@30.38,17.625 ; v3(30.825,21.8) C174.1@30.825,20.975 C175.1@29.925,20.975 C176.1@29.025,20.975 28.475,20.975 C173.1@27.9,21.55 27.7,21.55 27.2,22.05 27.225,22.075 ; C177.1@31.225,17.625 C178.1@30.38,17.625 ; v1(40.28,55.31) 40.535,55.31 41.155,55.93 C122.1@41.155,56.255 ; C122.1@41.155,56.265 C122.1@41.16,56.27 ; C134.2@41.91,45.08 41.93,45.1 v1(41.93,45.69) ; C131.2@41.91,47.2 41.93,47.22 v1(41.93,47.84) ; C130.2@41.91,49.3 41.93,49.32 v1(41.93,49.94) ; C128.2@41.91,51.51 41.93,51.53 v1(41.93,52.14) ; C126.2@41.91,53.72 41.93,53.74 v1(41.93,54.34) ; C120.2@41.925,57.75 41.875,57.8 v1(41.5,57.8) 41.335,57.8 41.16,57.625 C122.1@41.16,56.27 ; 45.125,11.425 45.176,11.476 CN16.7@46.48,11.476 47.651,11.476 47.7,11.525 ; C149.1@45.407,30.957 45.407,30.768 45.875,30.3 v1(46.6,30.3) ; v3(45.725,14.175) 46.455,14.904 CN16.6@49.02,14.904 50.329,14.904 51.075,15.65 v3(51.075,16.35) ; C156.1@46.35,28.975 46.35,29.725 46.425,29.8 46.425,30.125 v1(46.6,30.3) ; C148.1@47.75,31.175 47.75,31.034 47.016,30.3 v1(46.6,30.3) ; C148.1@47.812,31.333 48.144,31.665 v1(48.455,31.665) ; C163.1@48.448,27.284 48.433,27.269 v1@49.125,27.269 ; v1(48.455,29.065) 49.091,29.065 C155.1@49.261,29.234 ; v1(49.105,31.015) v1(49.755,30.365) 49.924,30.534 C150.1@50.561,30.534 50.561,30.1 ; v1(49.125,27.3) v1@49.125,27.269 ; v1(50.355,29.665) 50.561,29.871 50.561,30.1 ; v1(51.705,29.715) v1(51.055,29.065) 50.886,28.896 C159.1@50.886,28.259 ; v1(52.355,31.665) v1(51.705,31.015) 50.79,30.1 50.561,30.1 ; C147.1@53.8,31.275 53.475,30.95 v1(53.475,30.725) 53.475,30.5 C152.1@53.8,30.175 53.8,28.575 53.65,28.425 v1(53.65,28.2) 53.65,27.925 53.825,27.75 C191.1@53.825,27.55 ; C147.1@53.806,31.294 53.505,31.595 v1(53.505,31.865) 54.13,32.49 C139.1@54.255,32.49 ; v1(54.58,47.49) 55.02,47.93 R136.1@55.02,48.08 ; C135.2@58.47,44.24 58.51,44.28 v1(58.51,44.86) ; C132.2@58.47,47.01 58.51,47.05 v1(58.51,47.62) ; C129.2@58.47,49.59 58.48,49.6 v1(58.48,50.2) ; C127.2@58.47,51.74 58.48,51.75 v1(58.48,52.35) ; C125.2@58.49,53.83 v1(58.49,54.44) ; C119.2@58.575,57.75 58.595,57.73 v1(59.195,57.73) ; v1(59.03,55.19) 59.03,56.03 59.26,56.26 59.58,55.94 v1(59.58,55.18) ; 60.8,18.225 62.125,18.225 62.175,18.175 ; v3(60.825,48.8) R137.1@61.55,48.8 ; v3(61.5,17.325) 61.05,17.775 61.05,18.175 62.175,18.175 ; R129.1@61.55,51.35 61.6,51.4 v3(61.6,52.1) ; SB12.1@62.175,18.45 62.175,18.175 ; v3(63.244,61.469) CN13.7@63.244,63.164 ; v3(63.65,57.9) R119.1@63.65,57.2 64.8,57.2 T4.2@65.025,57.425 ; v3(64.4,12.8) 65.025,12.8 65.45,13.225 C184.1@65.8,13.225 C182.1@65.8,14.225 65.8,14.875 SB18.1@66.3,15.375 ; R139.1@64.625,47.75 64.625,48.25 64.9,48.525 v3(65.475,48.525) ; v3(65.375,30.475) C154.1@66.425,30.475 ; v3(65.68,27.965) 66.415,27.965 C164.1@66.425,27.975 ; v3(68.775,17.525) 68.775,18.7 R159.1@68.8,18.725 ; v3(69.925,21.2) C172.1@69.925,21.975 ; C142.1@70.425,32.475 71.33,33.38 v3(71.33,33.615) ; v3(71.925,21.2) C171.1@71.925,21.975 ; v3(72.825,21.2) C170.1@72.825,21.975 ; C186.1@73.25,10.675 v3(74.075,10.675) ; C141.1@73.925,32.475 73.925,32.875 74.1,33.05 v3(74.65,33.05) ; C181.1@75.2,17.225 75.55,17.225 v3(76.05,16.725) ; C169.1@75.425,21.975 75.708,21.692 v3(75.708,20.917) 75.95,20.675 75.95,20.175 ; C140.1@75.7,32.925 76.55,32.925 v3(76.875,32.6) ; v3(76.55,22.325) v3@76.575,22.35 ; R149.1@76.65,30.275 77.587,30.275 v3(77.662,30.2) ; C168.1@76.925,25.475 v3(77.7,25.475) ; C160.1@76.925,28.475 v3(77.7,28.475) ; v3(78.9,58.85) 79.725,58.025 C118.1@81.15,58.025 ; 79.8,44.675 79.825,44.65 C133.1@81.15,44.65 ; 79.85,54.875 79.9,54.925 C124.1@81.15,54.925 ; 80,40.675 80.025,40.65 C138.1@81.15,40.65 ; v3(81.1,53.5) 81.1,54.875 C124.1@81.15,54.925 ; v3(81.15,46) C133.1@81.15,44.65 ; 81.175,39.3 81.15,39.325 C138.1@81.15,40.65 ; 81.2,59.625 81.15,59.575 C118.1@81.15,58.025 ; 81.475,56.475 81.15,56.15 ; 82.125,57.575 81.525,57.575 C118.1@81.15,57.95 ; 82.4,44.675 82.375,44.65 C133.1@81.15,44.65 ; 82.425,40.525 82.3,40.65 C138.1@81.15,40.65 ; 82.525,54.925 C124.1@81.15,54.925 ; C136.1@83.475,43.125 C136.1@83.5,43.1 ; 93.3,40.475 93.325,40.5 U28.2@93.975,40.5 ; 93.325,58.45 U25.2@93.975,58.45 ; 93.35,42.1 U27.2@93.975,42.1 ; 93.425,60.05 U24.2@93.975,60.05 ; 93.975,39.625 U28.2@93.975,40.5 ; 93.975,60.85 U24.2@93.975,60.05 ; 94.025,42.975 93.975,42.925 U27.2@93.975,42.1 ; 94.025,57.575 93.975,57.625 U25.2@93.975,58.45 ; v3(94.8,40.5) U28.2@93.975,40.5 ; v3(94.8,42.1) U27.2@93.975,42.1 ; v3(94.8,58.45) U25.2@93.975,58.45 ; v3(94.8,60.05) U24.2@93.975,60.05 ; U30.2@95.025,26.275 v3(95.025,27.025) ; C167.1@96.225,26.025 C167.1@96.275,25.975 ; C167.1@96.275,25.925 C167.1@96.275,25.975 ; v3(96.275,26.725) C167.1@96.275,25.975 ; C166.1@97.625,26.725 v3(97.625,27.625) ; 27.225,22.075 v3(27.875,22.725) 27.225,22.075 ; C122.1@41.155,56.255 C122.1@41.16,56.26 ; C122.1@41.155,56.255 41.157,56.261 C122.1@41.16,56.27 ; C122.1@41.16,56.26 C122.1@41.16,56.27 ; C122.1@41.16,56.26 41.17,56.25 41.164,56.262 C122.1@41.16,56.27 ; v1@49.125,27.269 49.14,27.284 49.911,27.284 C159.1@50.886,28.259 ; C159.1@50.886,28.259 51.051,28.425 51.695,28.425 v1(51.705,28.415) C165.1@51.705,27.855 ; C165.1@51.705,27.855 51.65,27.8 51.705,27.745 C165.1@51.705,27.855 ; C138.1@81.15,40.65 C133.1@81.15,44.65 ; C124.1@81.15,54.925 81.15,56.15 ; 81.15,56.15 C118.1@81.15,57.95 ; C118.1@81.15,57.95 C118.1@81.15,58.025 ; U28.2@93.975,40.5 U27.2@93.975,42.1 ; U25.2@93.975,58.45 U24.2@93.975,60.05
  Bottom Layer w0.4: CN11.7@78,4.15 79,5.15 79,5.95 C190.1@79.45,6.4 ; 78,7.15 78,8.05 78.425,8.475 C188.1@79.425,8.475 ; C188.1@79.425,8.475 C187.1@79.425,9.775 ; C185.2@81.65,11.85 81.75,11.75 U34.2@81.75,10.225 v3(81.75,8.775) ; C189.1@83.125,6.625 83.125,5.9 83.25,5.775 v3(83.25,5.7)
  Bottom Layer w0.5: 81.475,56.475 C123.1@83.5,56.475 ; v3(82.325,43.125) C136.1@83.475,43.125 ; v3(82.675,59.575) C117.1@83.5,59.575 83.5,60.475 83.45,60.525 ; 82.8,42.275 82.875,42.2 C137.1@83.5,42.2 C136.1@83.5,43.1
  other v1: 39.65,2.625 68.075,3.425 0.75,3.75 3.5,3.75 17,3.75 22,3.75 27.25,3.75 43.75,3.75 80.25,3.75 83,3.75 85.25,3.75 92.5,3.75 97.25,3.75 100.25,3.75 6.475,3.775 31.15,4.8 100.25,5 7.75,5.75 13.25,6 17.25,6 0.75,6.25 4.75,7 96.375,7.3 100.25,7.5 0.75,9 21,9 11.5,9.25 97.5,9.75 100.25,9.75 21.5,10.5 8.5,11.5 100.25,12 98.1,12.175 12,12.25 0.75,12.5 18.75,13.5 4.75,14.75 100.25,14.75 8.25,15 20.75,15.25 0.75,15.75 11.5,16 19,17.25 5.75,17.5 97,17.5 9.75,18.25 88.75,18.5 0.75,19.25 100.25,19.5 11.5,20 19,20 90.75,21 20.25,21.5 14.5,21.75 100.25,21.75 95.5,22 89,22.5 0.75,23 3.75,24 100.25,24.5 0.75,26.5 100.25,27 94.5,29.25 100.25,29.25 5,29.75 0.75,30 100.25,31.5 0.75,33 5.75,34.25 95.25,34.25 100.25,34.25 97.5,35.25 0.75,36.25 100.25,36.75 97.25,39 100.25,39 10.75,40.75 100.25,41.25 11.75,42.5 19,42.75 97,43 92,43.5 100.25,43.75 45.91,43.95 95.25,45.25 92.25,45.5 100.25,46.25 83.5,46.5 97.5,47.25 93,47.75 81.5,48.25 100.25,48.5 89.75,49.25 95,49.5 13.25,49.75 18.5,49.75 84.25,49.75 81.25,50.25 11.5,50.75 100.25,50.75 97.5,51.25 95.25,51.75 82,52 20.5,52.75 22.75,52.75 78,53 85.5,53 89.75,53 94.5,53.25 16.75,53.5 18.5,53.5 100.25,53.5 31.125,54.225 32.875,54.225 34.6,54.225 20.5,54.75 48.83,54.74 97.5,54.75 24.25,54.801 32,54.875 33.725,54.875 95.25,55 31.125,55.45 34.6,55.475 89.75,56 100.25,56 32,56.075 33.725,56.075 20.5,56.5 72.25,56.5 31.15,56.65 32.875,56.65 34.6,56.65 17.5,56.75 23.75,56.75 95.25,56.75 76.225,57.8 97.75,58.25 100.25,58.25 20.5,58.75 17.5,59.25 45.025,59.45 63.75,59.5 76.75,59.5 46.975,59.575 54,59.75 59.5,59.75 48.725,60 100.25,60.5 84,60.75 85.75,60.75 96.75,61 91.75,61.25 17.5,61.5 81.75,62.25 19.75,62.5 60.65,62.725 83.5,62.75 95,63.25 100.25,63.25 92,63.5 97.75,63.5 17.5,63.75 21.25,64 19.75,65 83.5,65 85.75,65 17.5,65.75 100.25,65.75 92,66 97.5,66.25 94.5,66.5 19,67 84.25,67.5 90,67.5 17.5,68 100.25,68 95.25,68.25 97.75,68.25 19.25,69 17.5,70.25 20.25,70.25 24.5,70.25 75.5,70.25 78,70.25 82.75,70.25 85.25,70.25 88.75,70.25 91,70.25 94.5,70.25 96.5,70.25 98.5,70.25 100.25,70.25
  other v2: 0.475,1.5 2.975,1.5 17.975,1.5 20.475,1.5 22.975,1.5 25.475,1.5 27.975,1.5 30.475,1.5 32.975,1.5 37.975,1.5 40.475,1.5 42.975,1.5 45.475,1.5 47.975,1.5 50.475,1.5 52.975,1.5 55.475,1.5 57.975,1.5 60.475,1.5 62.975,1.5 65.475,1.5 67.975,1.5 70.475,1.5 72.975,1.5 77.975,1.5 80.475,1.5 82.975,1.5 85.475,1.5 90.475,1.5 92.975,1.5 97.975,1.5 1.725,4 4.225,4 9.225,4 11.725,4 14.225,4 26.725,4 31.725,4 34.225,4 44.225,4 49.225,4 51.725,4 54.225,4 56.725,4 59.225,4 61.725,4 69.225,4 71.725,4 79.225,4 86.725,4 94.225,4 96.725,4 99.225,4 2.975,6.5 5.475,6.5 7.975,6.5 12.975,6.5 15.475,6.5 17.975,6.5 25.475,6.5 27.975,6.5 30.475,6.5 32.975,6.5 35.475,6.5 62.975,6.5 65.475,6.5 72.975,6.5 77.975,6.5 85.475,6.5 95.475,6.5 97.975,6.5 1.725,9 4.225,9 19.225,9 21.725,9 29.225,9 31.725,9 34.225,9 39.225,9 51.725,9 54.225,9 56.725,9 61.725,9 64.225,9 66.725,9 79.225,9 96.725,9 99.225,9 0.475,11.5 2.975,11.5 5.475,11.5 7.975,11.5 10.475,11.5 22.975,11.5 25.475,11.5 52.975,11.5 72.975,11.5 90.475,11.5 95.475,11.5 97.975,11.5 1.725,14 4.225,14 6.725,14 9.225,14 11.725,14 16.725,14 59.225,14 69.225,14 71.725,14 79.225,14 81.725,14 96.725,14 99.225,14 0.475,16.5 2.975,16.5 5.475,16.5 7.975,16.5 10.475,16.5 70.475,16.5 72.975,16.5 87.975,16.5 90.475,16.5 92.975,16.5 97.975,16.5 1.725,19 9.225,19 11.725,19 51.725,19 74.225,19 89.225,19 91.725,19 94.225,19 96.725,19 99.225,19 0.475,21.5 5.475,21.5 12.975,21.5 15.475,21.5 17.975,21.5 67.975,21.5 70.475,21.5 75.475,21.5 77.975,21.5 87.975,21.5 90.475,21.5 92.975,21.5 97.975,21.5 1.725,24 6.725,24 11.725,24 79.225,24 91.725,24 96.725,24 5.475,26.5 22.975,26.5 67.975,26.5 75.475,26.5 82.975,26.5 90.475,26.5 95.475,26.5 97.975,26.5 1.725,29 4.225,29 21.725,29 39.225,29 81.725,29 84.225,29 89.225,29 96.725,29 99.225,29 0.475,31.5 2.975,31.5 7.975,31.5 27.975,31.5 30.475,31.5 32.975,31.5 35.475,31.5 37.975,31.5 40.475,31.5 77.975,31.5 85.475,31.5 95.475,31.5 1.725,34 4.225,34 6.725,34 14.225,34 19.225,34 89.225,34 91.725,34 94.225,34 96.725,34 99.225,34 5.475,36.5 7.975,36.5 32.975,36.5 35.475,36.5 40.475,36.5 62.975,36.5 67.975,36.5 70.475,36.5 90.475,36.5 95.475,36.5 97.975,36.5 6.725,39 19.225,39 29.225,39 31.725,39 34.225,39 39.225,39 59.225,39 64.225,39 66.725,39 69.225,39 84.225,39 89.225,39 96.725,39 99.225,39 2.975,41.5 5.475,41.5 7.975,41.5 10.475,41.5 17.975,41.5 22.975,41.5 27.975,41.5 30.475,41.5 32.975,41.5 37.975,41.5 60.475,41.5 62.975,41.5 80.475,41.5 85.475,41.5 90.475,41.5 92.975,41.5 95.475,41.5 97.975,41.5 1.725,44 16.725,44 19.225,44 31.725,44 59.225,44 71.725,44 91.725,44 94.225,44 96.725,44 99.225,44 32.375,45.7 34.325,45.825 12.975,46.5 22.975,46.5 32.975,46.5 70.475,46.5 72.975,46.5 77.975,46.5 80.475,46.5 82.975,46.5 92.975,46.5 95.475,46.5 97.975,46.5 35.75,46.6 29.4,47.45 30.3,47.45 26.775,48.075 33.375,48.2 34.05,48.2 27.675,48.625 29.175,48.85 30.325,48.85 4.225,49 19.225,49 39.225,49 41.725,49 59.225,49 61.725,49 76.725,49 89.225,49 96.725,49 99.225,49 28.825,49.175 31.05,49.65 34.825,49.625 36.325,49.625 26.8,50.4 27.55,50.4 28.911,51.125 37.075,51.325 10.475,51.5 15.475,51.5 17.975,51.5 22.975,51.5 70.475,51.5 75.475,51.5 82.975,51.5 90.475,51.5 97.975,51.5 9.225,54 19.225,54 21.725,54 39.225,54 59.225,54 71.725,54 76.725,54 89.225,54 96.725,54 99.225,54 10.475,56.5 17.975,56.5 22.975,56.5 60.475,56.5 62.975,56.5 65.475,56.5 67.975,56.5 70.475,56.5 75.475,56.5 80.475,56.5 90.475,56.5 97.975,56.5 33.075,58.5 6.725,59 9.225,59 11.725,59 16.725,59 19.225,59 21.725,59 24.225,59 44.225,59 46.725,59 49.225,59 51.725,59 54.225,59 56.725,59 59.225,59 64.225,59 69.225,59 71.725,59 81.725,59 91.725,59 94.225,59 96.725,59 99.225,59 34.8,59.425 27.9,60.375 28.475,60.375 27.45,60.8 34.8,61 26.85,61.35 20.475,61.5 25.475,61.5 42.975,61.5 45.475,61.5 47.975,61.5 50.475,61.5 52.975,61.5 55.475,61.5 60.475,61.5 67.975,61.5 70.475,61.5 72.975,61.5 75.475,61.5 80.475,61.5 82.975,61.5 85.475,61.5 92.975,61.5 95.475,61.5 97.975,61.5 31.65,61.65 32.825,61.65 26.325,61.85 27.7,62.175 26.375,62.55 34.2,62.775 24.975,62.8 23.4,62.825 27.05,62.925 16.725,64 19.225,64 36.725,64 44.225,64 46.725,64 49.225,64 51.725,64 54.225,64 64.225,64 66.725,64 69.225,64 71.725,64 74.225,64 76.725,64 79.225,64 89.225,64 91.725,64 94.225,64 96.725,64 99.225,64 17.975,66.5 85.475,66.5 87.975,66.5 95.475,66.5 97.975,66.5 16.725,69 59.225,69 64.225,69 66.725,69 71.725,69 74.225,69 84.225,69 89.225,69 96.725,69 99.225,69
  other v3: 42.8,11.275 45.4,11.275 42.775,14.375 29.3,22.75 30.85,24.3 27.775,24.325 73.525,24.6 74.225,29.8 69.1,29.825 27.18,34.69 75.45,36.3 76.45,36.3 77.45,36.3 76.45,37.3 77.45,37.3 75.45,38.3 76.45,38.3 77.45,38.3 0.7,38.7 1.8,38.7 3.225,38.7 4.675,38.7 6.15,38.7 7.625,38.7 82.475,39.75 0.7,39.825 6.125,40.7 0.7,41.075 0.7,42.425 0.7,43.7 0.7,46.2 0.7,47.325 65.375,47.525 66.975,47.525 68.6,47.55 67.85,48.4 66.625,48.425 0.7,48.55 68.6,49.35 68.525,50.4 67.65,50.8 10.15,53.8 11.4,53.8 12.725,53.8 13.95,53.8 5.4,53.9 15.2,54.3 13.95,54.875 0.725,54.9 6.25,55.275 7.425,55.275 8.575,55.275 9.825,55.275 11.125,55.275 12.525,55.275 15.2,55.5 4.025,55.7 0.725,55.875 1.925,55.875 13.95,56.075 5,56.375 6.25,56.375 7.425,56.375 8.575,56.375 9.825,56.375 11.125,56.375 12.525,56.375 0.725,56.75 15.2,56.75 1.925,56.775 4.025,56.925 6.25,57.375 7.425,57.375 8.575,57.375 9.825,57.375 11.125,57.375 12.525,57.375 13.95,57.4 0.725,57.725 2.025,57.725 15.2,57.9 4.975,58.475 6.25,58.475 7.425,58.475 8.575,58.475 9.825,58.475 11.125,58.475 12.525,58.475 13.95,58.475 3.9,58.525 0.725,58.7 2.2,58.7 15.2,58.975 13.95,59.5 3.75,59.575 5,59.575 6.25,59.575 7.425,59.575 8.575,59.575 9.825,59.575 11.125,59.575 12.525,59.575 2.2,59.6 0.725,59.625 15.2,60.075 0.725,60.575 2.2,60.575 3.75,60.575 5,60.575 6.25,60.575 7.425,60.575 8.575,60.575 9.825,60.575 11.125,60.575 12.525,60.575 13.95,60.575 15.2,61.225 15.2,62.325 15.2,63.525 65.75,63.875 15.2,64.675 15.2,65.825 15.2,66.9 15.2,68 15.2,69.1 15.2,70.25
  other v4: 52.83,35.44 27.325,47.5 28.35,47.5 26.275,48.95 26.275,49.8
HDMI_CEC: U13.Y14 U14.50 | length 35.2
  Top Layer w0.1: v4(53.28,32.29) 53.575,32.29 53.88,31.985 53.88,31.89 U13.Y14@54.08,31.69 ; U14.50@73.925,22.425 v1(73.925,23.375)
  Signal Layer 1 w0.1: v4(53.28,32.29) 53.575,32.29 53.7,32.165 53.944,32.165 54.019,32.24 60.176,32.24 60.601,32.665 61.655,32.665 61.955,32.365 63.58,32.365 66.18,34.965 v1(66.43,34.965)
  Bottom Layer w0.1: v1(66.43,34.965) 66.43,34.821 66.935,34.316 68.173,34.316 68.773,34.915 70.105,34.915 70.681,34.34 72.589,34.34 73.156,33.773 73.156,25.605 73.975,24.786 73.975,23.425 v1(73.925,23.375)
HDMI_INT: U13.W1 U14.52 | length 29.6
  Top Layer w0.1: U13.W1@53.58,25.19 53.58,24.87 54.5,23.95 54.691,23.95 54.866,23.775 58.809,23.775 59.106,23.479 60.323,23.479 61.061,22.74 62.449,22.74 63.43,23.721 v1(63.43,24.69) ; 74.925,21.69 U14.52@74.925,22.425 ; 74.93,21.69 75.13,21.49 v1(75.13,20.34)
  Signal Layer 3 w0.1: v1(63.43,24.69) 63.43,22.195 65.285,20.34 v1(75.13,20.34)
HDMI_NRST: R40.2 U13.Y17 U14.51 | length 41
  Top Layer w0.1: U13.Y17@54.08,33.19 v2(54.33,33.44) ; U14.51@74.425,22.425 74.425,21.245 74.625,21.045 v1(74.73,20.94)
  Top Layer w0.3: v1(61.5,36.2) R40.2@61.5,36.875
  Signal Layer 1 w0.1: v2(54.33,33.44) 54.719,33.44 55.019,33.74 56.79,33.74 57.55,34.5 57.55,34.885 59.065,36.4 61.3,36.4 v1(61.5,36.2)
  Bottom Layer w0.1: v1(61.5,36.2) 60.925,35.625 60.925,33.665 61.075,33.515 63.255,33.515 64.005,32.765 65.476,32.765 66.827,34.116 68.256,34.116 68.855,34.715 70.022,34.715 70.598,34.14 72.05,34.14 72.33,33.86 72.33,31.815 72.956,31.189 72.956,24.464 73.555,23.865 73.555,23.065 74.73,21.89 v1(74.73,20.94)
HPD: CN9.19 R164.2 U14.54 U33.4 | length 33.7
  Top Layer w0.2: U14.54@75.925,22.35 75.925,21.75 76.975,20.7 76.975,17.186 79.061,15.1 83.225,15.1 85.975,12.35 85.975,10.025 87.4,8.6 v1(88.15,8.6) ; v1(88.575,7.575) 88.375,7.375 88.375,4.675 89,4.05 91.45,4.05 92.65,5.25 CN9.19@93.5,5.25
  Bottom Layer w0.2: v1(88.15,8.6) 88.575,8.175 v1(88.575,7.575) R164.2@88.575,6.85 U33.4@89.75,6.85
HSE_IN: C88.2 U13.P1 X6.3 | length 5.5
  Top Layer w0.1: U13.P1@51.08,25.19 51.08,24.099 52.254,22.925 52.254,22.371 52.95,21.675 C88.2@53.1,21.675 ; C88.2@53.1,21.625 53.1,20.725 X6.3@53.2,20.625
HSE_OUT: R73.2 R303.1 U13.P2 | length 5.9
  Top Layer w0.09: 50.83,24.067 50.83,25.44 U13.P2@51.08,25.69
  Top Layer w0.1: 50.83,24.067 51.925,22.972 51.925,22.175 52.2,21.9 52.2,20.55 R73.2@52.25,20.5
I2C1_SCL: CN2.28 CN4.11 R1.2 R85.2 SB8.1 U13.Y18 U14.1 | length 211.6
  Top Layer w0.1: CN4.11@24.425,42 25.85,42 v1(25.875,42.025) ; R85.2@39.65,15.075 v1(39.65,15.65) ; U13.Y18@54.08,33.69 v2(54.33,33.94) ; v1(59.1,65.575) 59.1,64.5 58.325,63.725 58.325,61.525 58.85,61 R1.2@58.95,61 59,61 61.35,58.65 61.35,53.508 60.2,52.358 60.2,49.975 60.435,49.74 v1(60.78,49.74) ; v1@71.575,41.3 71.755,41.12 71.755,35.74 73.745,33.75 75.425,33.75 75.925,33.25 U14.1@75.925,32.1
  Top Layer w0.3: CN4.11@20.675,42 CN4.11@24.425,42
  Signal Layer 1 w0.1: v2(54.33,33.94) 54.355,33.94 54.703,34.288 55.088,34.288 59.04,38.24 60.371,38.24 60.511,38.1 62.19,38.1 63.18,39.09 v1(63.18,39.19)
  Signal Layer 2 w0.1: v1(21.98,63.49) 23.261,63.49 24.386,64.615 25.615,64.615 25.975,64.975 25.975,67.225 26.345,67.595 31.055,67.595 31.275,67.375 31.275,65.743 31.475,65.543 31.475,62.784 32.069,62.19 32.441,62.19 32.716,62.464 36.114,62.464 37.4,63.75 42.846,63.75 43.406,63.19 47.265,63.19 48.93,64.855 58.38,64.855 v1(59.1,65.575)
  Signal Layer 3 w0.1: v1(21.98,63.49) 21.575,63.085 21.575,46.333 25.875,42.033 v1(25.875,42.025) ; v1(39.65,15.65) 39.635,15.665 v1@39.655,15.665 ; v1(59.1,65.575) 59.1,67.48 CN2.28@60.39,68.77 ; v1(63.4,17.4) 63.75,17.75 63.75,19.442 63.755,19.447 63.755,21.323 63.075,22.003 63.075,24.83 63.285,25.04 63.515,25.04 64.9,26.425 65.933,26.425 66.456,26.948 66.456,33.538 70.168,37.25 70.469,37.25 71.55,38.331 v1(71.55,41.3)
  Bottom Layer w0.1: v1(39.65,15.65) 40.092,15.208 40.859,15.208 42.72,13.347 44.903,13.347 45.275,12.975 50.089,12.975 50.264,13.15 52.5,13.15 53.35,12.3 54.42,12.3 54.66,12.54 55.427,12.54 57.281,14.393 57.281,15.86 57.682,16.261 61.994,16.261 63.133,17.4 v1(63.4,17.4) ; v1(60.78,49.74) 61.415,50.375 66.675,50.375 66.8,50.25 66.8,49.95 66.7,49.85 ; v1(63.18,39.19) 68.565,39.19 69.75,40.375 70.165,40.375 71.09,41.3 v1(71.55,41.3) 71.8,41.05 73.625,41.05 74.9,42.325 74.9,43.617 72.575,45.942 72.575,46.675 69.4,49.85 66.7,49.85 ; 66.35,49.85 66.7,49.85
I2C1_SDA: CN2.27 CN4.12 R2.2 R86.2 SB7.1 U13.Y4 U14.2 | length 199
  Top Layer w0.1: CN4.12@24.425,43 25.403,43 v1(25.876,42.527) ; R86.2@40.7,15.075 v1(40.7,15.65) ; v2(53.83,26.94) U13.Y4@54.08,26.69 ; R2.2@59.875,61 60.05,61.175 60.65,61.175 61.05,61.575 61.05,63.675 60.39,64.335 CN2.27@60.39,66.23 ; R2.2@60.125,60.85 61.55,59.425 61.55,53.425 60.4,52.275 60.4,50.545 v1(60.58,50.365) ; v1@71.162,40.812 71.555,40.42 71.555,35.657 73.662,33.55 75.15,33.55 75.425,33.275 U14.2@75.425,32.025
  Top Layer w0.3: CN4.12@20.675,43 CN4.12@24.425,43
  Signal Layer 1 w0.1: v2(53.83,26.94) 53.805,26.915 53.805,25.632 54.222,25.215 54.446,25.215 57.321,22.34 57.423,22.34 57.98,21.783 57.98,20.997 56.631,19.647 56.631,19.304 56.632,19.303 56.632,18.847 56.631,18.846 56.631,18.661 56.605,18.635 56.605,18.345 56.613,18.338 55.825,17.55 v1(55.85,17.525)
  Signal Layer 2 w0.1: v1(22.425,62.95) 23.004,62.95 24.469,64.415 25.735,64.415 26.25,63.9 28.935,63.9 29.935,64.9 30.245,64.9 30.655,65.31 30.945,65.31 31.275,64.98 31.275,62.701 32.226,61.75 36,61.75 37.8,63.55 42.764,63.55 43.599,62.715 47.211,62.715 49.151,64.655 58.815,64.655 CN2.27@60.39,66.23
  Signal Layer 3 w0.1: v1(22.425,62.95) 22.025,62.95 21.775,62.7 21.775,46.628 v1(25.876,42.527) ; v1(55.85,17.525) 55.85,16.325 56.325,15.85 v1(56.325,14.075) ; v1(63.4,17.95) 63.45,17.95 63.55,18.05 63.55,19.675 ; 63.555,19.675 63.555,21.24 62.875,21.92 62.875,24.913 63.455,25.493 63.455,26.085 63.66,26.29 64.482,26.29 64.817,26.625 65.85,26.625 66.256,27.031 66.256,29.261 66.255,29.262 66.255,33.62 70.085,37.45 70.386,37.45 71.35,38.414 71.35,40.625 71.175,40.8 v1(71.175,40.825)
  Bottom Layer w0.1: v1(40.7,15.65) 42.803,13.547 44.985,13.547 45.358,13.175 50.006,13.175 50.181,13.35 52.583,13.35 53.433,12.5 54.337,12.5 54.577,12.74 55.344,12.74 56.35,13.746 56.35,14.05 v1(56.325,14.075) ; v1(55.85,17.525) 56.175,17.525 56.325,17.375 60.05,17.375 60.775,16.65 62.1,16.65 v1(63.4,17.95) ; v1(60.58,50.365) 61.122,50.365 61.332,50.575 66.475,50.575 66.575,50.675 66.575,51.35 ; 66.625,51.625 SB7.1@66.35,51.35 66.575,51.35 ; v1(71.175,40.825) 71.2,40.85 73.708,40.85 75.1,42.242 75.1,43.7 72.775,46.025 72.775,46.786 68.211,51.35 66.575,51.35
